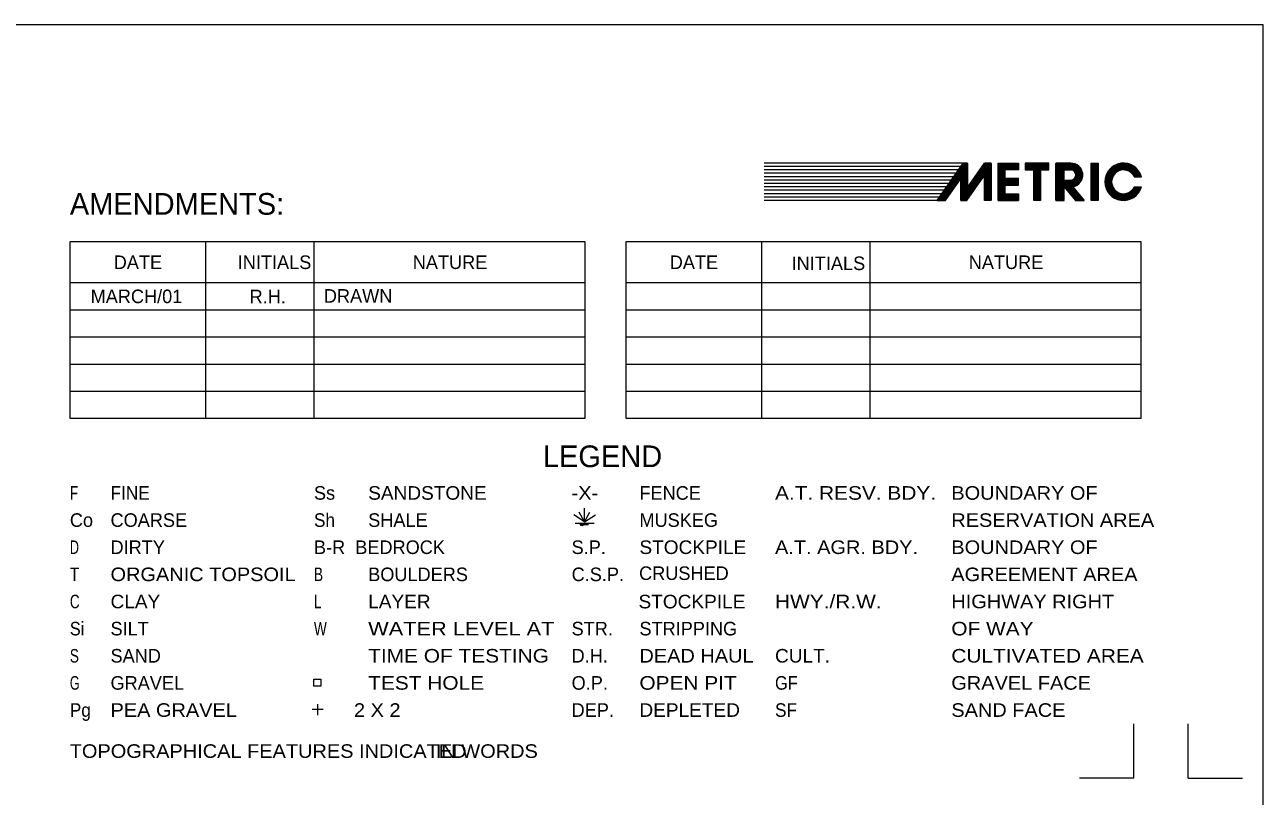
# Model space of a CAD drawing. Extents: x -496 to 480, y -450 to 700.
# Drawn here: x -6.6 to 450, y 415.7 to 700 of the extents above; entities that cross this region are included whole.
import ezdxf
from ezdxf.enums import TextEntityAlignment as Align

# ---------------------------------------------------------------- set-up
doc = ezdxf.new("R2010")
doc.units = 0
doc.header["$LTSCALE"] = 2
doc.header["$PDMODE"] = 32
doc.header["$PDSIZE"] = 1
doc.layers.add('1', color=7, linetype='Continuous', lineweight=13)

msp = doc.modelspace()

# ---------------------------------------------------------------- linework, layer by layer
at = {"layer": '1'}
for p, q in [((339.376, 648.989), (265.976, 648.989)), ((329.726, 635.239), (339.376, 648.989)), ((340.976, 640.064), (347.226, 648.989)), ((349.726, 648.989), (347.226, 648.989)), ((349.726, 635.239), (349.726, 648.989)), ((362.226, 648.989), (362.226, 646.489)), ((379.026, 648.989), (373.476, 648.989)), ((338.501, 647.739), (265.976, 647.739)), ((337.626, 646.489), (265.976, 646.489)), ((336.751, 645.239), (265.976, 645.239)), ((335.876, 643.989), (265.976, 643.989)), ((340.676, 635.264), (347.226, 644.614)), ((347.226, 635.239), (347.226, 644.614)), ((354.726, 646.489), (354.726, 643.364)), ((362.226, 646.489), (365.351, 646.489)), ((367.851, 646.489), (370.976, 646.489)), ((376.601, 646.489), (379.151, 646.489)), ((376.601, 642.739), (376.601, 646.489)), ((402.426, 643.989), (405.076, 643.989)), ((335.001, 642.739), (265.976, 642.739)), ((334.126, 641.489), (265.976, 641.489)), ((333.251, 640.239), (265.976, 640.239)), ((332.776, 635.239), (338.476, 643.364)), ((338.476, 635.239), (338.476, 643.389)), ((354.726, 640.864), (354.726, 637.739)), ((376.601, 642.739), (379.151, 642.739)), ((376.601, 640.239), (380.726, 635.239)), ((376.601, 635.239), (376.601, 640.239)), ((379.801, 640.289), (383.951, 635.239)), ((402.426, 640.239), (405.101, 640.239)), ((332.376, 638.989), (265.976, 638.989)), ((331.501, 637.739), (265.976, 637.739)), ((330.626, 636.489), (265.976, 636.489)), ((329.726, 635.239), (265.976, 635.239)), ((329.726, 635.239), (332.776, 635.239)), ((338.476, 635.239), (340.676, 635.239)), ((349.726, 635.239), (347.226, 635.239)), ((352.226, 635.239), (359.726, 635.239)), ((380.726, 635.239), (383.951, 635.239)), ((199.983, 619.973), (9.983, 619.973)), ((9.983, 619.973), (9.983, 554.973)), ((59.983, 619.973), (59.983, 554.973)), ((99.983, 619.973), (99.983, 554.973)), ((199.983, 554.973), (199.983, 619.973)), ((404.983, 619.973), (214.983, 619.973)), ((214.983, 619.973), (214.983, 554.973)), ((264.983, 619.973), (264.983, 554.973)), ((304.983, 619.973), (304.983, 554.973)), ((404.983, 554.973), (404.983, 619.973)), ((9.983, 604.973), (199.983, 604.973)), ((214.983, 604.973), (404.983, 604.973)), ((9.983, 594.973), (199.983, 594.973)), ((214.983, 594.973), (404.983, 594.973)), ((9.983, 584.973), (199.983, 584.973)), ((214.983, 584.973), (404.983, 584.973)), ((9.983, 574.973), (199.983, 574.973)), ((214.983, 574.973), (404.983, 574.973)), ((9.983, 564.973), (199.983, 564.973)), ((214.983, 564.973), (404.983, 564.973)), ((214.983, 554.973), (404.983, 554.973)), ((199.76, 516.875), (199.76, 521.875)), ((199.76, 516.875), (195.76, 519.375)), ((196.26, 516.375), (203.26, 516.375)), ((199.76, 516.875), (197.76, 520.375)), ((199.76, 516.875), (201.76, 520.375)), ((199.76, 516.875), (203.76, 519.375)), ((198.26, 515.875), (201.26, 515.875)), ((103.353, 447.618), (99.353, 447.618)), ((101.291, 449.597), (101.291, 445.597)), ((402.281, 422.339), (402.281, 442.339)), ((422.281, 422.339), (422.281, 442.339)), ((402.281, 422.339), (382.281, 422.339)), ((422.281, 422.339), (442.281, 422.339))]:
    msp.add_line(p, q, dxfattribs=at)
for points in [[(449.983, -450.027), (449.983, 399.973), (449.983, 699.973), (-450.017, 699.973), (-450.017, 49.973), (-450.017, -450.027)], [(329.901, 635.339), (339.401, 648.889), (340.901, 648.889), (340.901, 639.839), (347.251, 648.839), (349.626, 648.889), (349.676, 635.339), (347.351, 635.314), (347.301, 644.789), (340.576, 635.339), (338.576, 635.314), (338.576, 643.539), (332.701, 635.339), (330.076, 635.314), (339.501, 648.739), (340.801, 648.739), (340.776, 639.664), (347.276, 648.664), (349.526, 648.739), (349.651, 635.564), (347.501, 635.464), (347.426, 644.989), (340.526, 635.489), (338.726, 635.439), (338.676, 643.764), (332.651, 635.464), (330.301, 635.439), (339.576, 648.539), (340.651, 648.564), (340.651, 639.489), (347.351, 648.489), (349.301, 648.564), (349.476, 635.739), (347.726, 635.639), (347.626, 645.314), (340.451, 635.714), (338.926, 635.639), (338.876, 644.139), (332.501, 635.689), (330.701, 635.639)], [(340.976, 640.039), (340.976, 648.989), (339.376, 648.989)], [(352.226, 635.239), (352.226, 648.989), (359.726, 648.989)], [(352.376, 648.914), (359.651, 648.864), (359.676, 646.614), (354.626, 646.589), (354.626, 643.289), (359.651, 643.289), (359.651, 640.989), (354.651, 640.939), (354.626, 637.614), (359.676, 637.639), (359.651, 635.339), (352.351, 635.314), (352.376, 648.789), (359.551, 648.739), (359.551, 646.764), (354.501, 646.714), (354.501, 643.214), (359.551, 643.164), (359.551, 641.114), (354.551, 641.064), (354.526, 637.439), (359.551, 637.514), (359.501, 635.439), (352.501, 635.439), (352.576, 648.639), (359.401, 648.564), (359.426, 646.914), (354.376, 646.839), (354.351, 643.064), (359.426, 643.039), (359.376, 641.289), (354.401, 641.239), (354.376, 637.239), (359.401, 637.339), (359.376, 635.589), (352.701, 635.614), (352.726, 648.439), (359.226, 648.414), (359.251, 647.064), (354.251, 647.039)], [(359.726, 648.989), (359.726, 646.489), (354.726, 646.489)], [(370.976, 646.489), (370.976, 648.989), (362.226, 648.989)], [(362.351, 648.864), (370.851, 648.889), (370.851, 646.639), (367.701, 646.639), (367.751, 635.414), (365.451, 635.314), (365.451, 646.564), (362.351, 646.589), (362.351, 648.764), (370.801, 648.789), (370.726, 646.789), (367.601, 646.764), (367.676, 635.539), (365.576, 635.414), (365.626, 646.739), (362.476, 646.739), (362.476, 648.639), (370.626, 648.639), (370.576, 646.989), (367.426, 646.864), (367.526, 635.739), (365.751, 635.614), (365.776, 646.864), (362.701, 646.939), (362.726, 648.439), (370.451, 648.489), (370.376, 647.114), (367.276, 646.989), (367.376, 635.914), (365.901, 635.789), (365.951, 647.064), (362.901, 647.114), (362.901, 648.264), (370.201, 648.289), (370.201, 647.364), (367.076, 647.189), (367.226, 636.114), (366.126, 635.989), (366.101, 647.264), (363.101, 647.314)], [(373.476, 648.989), (373.476, 635.239), (376.601, 635.239)], [(373.601, 648.914), (378.976, 648.889), (380.101, 648.739), (381.101, 648.364), (381.826, 647.789), (382.451, 647.189), (382.901, 646.414), (383.301, 645.389), (383.301, 644.439), (383.126, 643.214), (382.651, 642.314), (381.926, 641.489), (381.051, 640.889), (380.401, 640.639), (379.651, 640.389), (380.026, 639.714), (380.576, 639.189), (383.701, 635.339), (380.801, 635.314), (376.501, 640.464), (376.526, 635.339), (373.551, 635.314), (373.551, 648.864), (379.026, 648.789), (380.076, 648.639), (380.926, 648.314), (382.276, 647.214), (383.151, 645.364), (383.026, 643.314), (382.601, 642.464), (381.901, 641.614), (381.051, 640.989), (379.576, 640.464), (383.501, 635.414), (380.951, 635.439), (376.351, 640.739), (376.401, 635.489), (373.701, 635.439), (373.701, 648.739), (379.151, 648.664), (380.076, 648.489), (380.851, 648.189), (382.126, 647.139), (383.026, 645.389), (382.951, 643.539), (382.501, 642.564), (381.901, 641.739), (381.051, 641.114), (379.401, 640.614), (383.201, 635.564), (381.001, 635.564), (376.226, 640.889), (376.276, 635.614), (373.826, 635.539), (373.826, 648.614), (379.126, 648.489), (380.676, 648.089), (382.026, 647.139), (382.876, 645.439), (382.801, 643.664), (382.401, 642.664), (381.801, 641.889), (380.951, 641.189), (379.226, 640.764), (382.901, 635.689), (381.101, 635.689), (376.051, 641.064), (376.126, 635.789), (373.976, 635.689), (373.976, 648.439), (379.101, 648.364), (380.551, 647.989), (381.851, 647.089), (382.776, 645.439), (382.701, 643.764), (382.326, 642.889), (381.726, 642.064), (380.901, 641.339), (379.026, 640.939), (382.601, 635.789), (381.126, 635.814), (375.876, 641.239), (375.976, 635.939), (374.126, 635.864), (374.126, 648.239), (379.026, 648.239), (380.251, 647.914), (381.676, 647.014), (382.576, 645.414), (382.601, 643.914), (382.276, 642.989), (381.651, 642.214), (380.826, 641.514), (378.851, 641.064), (382.351, 635.939), (381.176, 635.989), (375.776, 641.514), (375.826, 636.089), (374.251, 636.014), (374.276, 648.039), (378.976, 648.114)], [(386.776, 648.839), (388.951, 648.864), (389.001, 635.364), (386.701, 635.364), (386.676, 648.739), (388.851, 648.764), (388.876, 635.489), (386.826, 635.439), (386.801, 648.614), (388.776, 648.639), (388.776, 635.664), (386.976, 635.589), (386.926, 648.464), (388.626, 648.464), (388.601, 635.764), (387.126, 635.764), (387.101, 648.364), (388.501, 648.364), (388.451, 635.939), (387.301, 635.964), (387.301, 648.214), (388.401, 648.214), (388.301, 636.089), (387.426, 636.089), (387.476, 648.064), (388.251, 648.039), (388.151, 636.214), (387.576, 636.214), (387.676, 647.914), (388.126, 647.889), (388.001, 636.339), (387.776, 636.389), (387.826, 647.764), (387.976, 647.714), (387.901, 636.539)], [(404.901, 644.089), (404.451, 645.189), (403.851, 646.164), (403.151, 646.914), (402.301, 647.639), (401.151, 648.289), (400.126, 648.614), (398.801, 648.814), (397.351, 648.689), (395.876, 648.339), (394.601, 647.639), (393.601, 646.764), (392.776, 645.664), (392.176, 644.564), (391.801, 642.964), (391.801, 641.264), (392.176, 639.789), (392.726, 638.564), (393.351, 637.739), (394.101, 637.014), (394.976, 636.389), (395.901, 635.914), (397.126, 635.489), (398.726, 635.389), (400.151, 635.589), (401.301, 635.989), (402.326, 636.564), (403.326, 637.414), (404.001, 638.264), (404.426, 639.139), (404.801, 640.064), (402.526, 640.089), (401.776, 638.989), (400.776, 638.289), (399.801, 637.814), (398.476, 637.564), (397.026, 637.839), (396.126, 638.289), (395.276, 638.939), (394.551, 639.939), (394.076, 641.189), (394.051, 642.814), (394.276, 643.889), (394.901, 644.889), (395.601, 645.614), (396.476, 646.164), (397.376, 646.489), (398.426, 646.614), (399.526, 646.489), (400.426, 646.214), (401.176, 645.764), (401.801, 645.239), (402.301, 644.664), (402.576, 644.139), (404.726, 644.164), (404.251, 645.214), (403.651, 646.164), (402.276, 647.489), (401.126, 648.114), (399.351, 648.614), (397.876, 648.564), (396.551, 648.339), (395.226, 647.814), (394.351, 647.264), (393.451, 646.339), (392.676, 645.139), (392.176, 643.939), (391.976, 642.239), (392.076, 640.689), (392.576, 639.164), (393.476, 637.864), (394.526, 636.864), (395.701, 636.164), (397.201, 635.639), (398.626, 635.514), (400.251, 635.764), (401.276, 636.089), (402.301, 636.789), (403.176, 637.439), (403.726, 638.164), (404.376, 639.239), (404.551, 639.964), (402.626, 639.989), (402.076, 639.064), (400.751, 638.139), (399.826, 637.689), (398.526, 637.389), (396.976, 637.739), (395.601, 638.439), (394.651, 639.639), (394.076, 640.764), (393.876, 642.139), (394.151, 643.989), (394.726, 644.964), (395.826, 646.014), (397.051, 646.539), (398.351, 646.789), (399.826, 646.614), (401.026, 646.064), (401.701, 645.614), (402.226, 645.014)], [(402.226, 645.014), (402.301, 645.014), (402.676, 644.239), (404.476, 644.264), (404.026, 645.314), (402.876, 646.664), (401.901, 647.489), (400.851, 648.089), (399.251, 648.514), (396.976, 648.264), (395.201, 647.614), (394.051, 646.639), (393.151, 645.614), (392.526, 644.239), (392.176, 642.439), (392.326, 640.539), (392.676, 639.489), (392.951, 638.864), (393.701, 637.864), (394.851, 636.839), (397.101, 635.814), (398.651, 635.664), (401.026, 636.164), (403.076, 637.564), (403.901, 638.814), (404.326, 639.814), (403.476, 639.789), (402.726, 639.839), (402.201, 638.889), (400.776, 637.964), (399.526, 637.414), (398.251, 637.264), (396.651, 637.714), (395.476, 638.364), (394.451, 639.714), (393.901, 640.864), (393.701, 642.264), (393.976, 643.889), (394.651, 645.264), (395.701, 646.214), (397.376, 646.789), (398.851, 646.914), (400.251, 646.614), (401.626, 645.914), (402.426, 645.164), (402.801, 644.439), (404.226, 644.414), (403.426, 645.739), (402.676, 646.614), (401.826, 647.314), (400.851, 647.939), (399.276, 648.314), (397.051, 648.089), (395.226, 647.364), (393.976, 646.314), (393.201, 645.414), (392.651, 643.839), (392.426, 642.514), (392.451, 641.239), (392.651, 640.089), (393.101, 639.039), (393.651, 638.239), (394.376, 637.564), (395.226, 636.839), (396.351, 636.314), (397.451, 635.914), (398.701, 635.839), (400.826, 636.364), (402.976, 637.639), (403.801, 638.964), (404.026, 639.714), (402.851, 639.664), (402.326, 638.814), (401.226, 638.164), (399.651, 637.239), (398.226, 637.114), (397.101, 637.389), (395.976, 637.889), (394.801, 638.989), (394.101, 640.014), (393.601, 641.664), (393.676, 643.264), (394.101, 644.689), (395.376, 646.214), (396.876, 646.764), (398.751, 647.064), (400.326, 646.764), (401.751, 646.089), (402.651, 645.189), (402.951, 644.539), (403.876, 644.614), (403.051, 645.989), (402.201, 646.789), (400.851, 647.739), (399.376, 648.189), (397.151, 647.889), (395.451, 647.239), (394.076, 646.164), (393.251, 645.039), (392.701, 643.014), (392.651, 641.564)], [(330.701, 635.639), (339.651, 648.239), (340.326, 648.264), (340.476, 639.239), (347.526, 648.239), (349.126, 648.289), (349.226, 635.939), (348.001, 635.939), (347.851, 645.664), (340.326, 635.989), (339.151, 635.864), (339.126, 644.464), (332.401, 635.939), (331.076, 635.839), (339.651, 647.914), (340.151, 647.914), (340.251, 638.889), (347.601, 647.964), (348.926, 648.014), (349.026, 636.164), (348.251, 636.139), (348.051, 646.014), (340.226, 636.239), (339.351, 636.089), (339.326, 644.789), (332.226, 636.164), (331.476, 636.064), (339.701, 647.664), (339.926, 647.689), (340.126, 638.764), (347.751, 647.839), (348.701, 647.739), (348.826, 636.364), (348.476, 636.364), (348.176, 646.314), (340.126, 636.464), (339.551, 636.339), (339.426, 645.114), (332.201, 636.339), (331.851, 636.289)], [(331.851, 636.289), (339.701, 647.264), (339.926, 638.564), (347.826, 647.614), (348.451, 647.589), (348.701, 636.589), (348.251, 646.639), (340.126, 636.689), (339.726, 636.589), (339.576, 645.539), (332.301, 636.639), (339.526, 646.714), (339.576, 645.814), (335.101, 640.239), (339.401, 646.164), (339.401, 645.914), (338.176, 644.289)], [(339.901, 638.414), (339.926, 636.839), (348.276, 646.889), (348.326, 647.439), (347.951, 647.439), (340.126, 638.539), (340.151, 637.314), (348.176, 647.064), (348.051, 647.214), (340.326, 638.539), (340.401, 637.839), (347.851, 646.839), (340.501, 638.639), (340.526, 638.389), (344.426, 642.914)], [(354.251, 647.039), (354.176, 642.864), (359.251, 642.864), (359.176, 641.439), (354.251, 641.389), (354.201, 637.064), (359.201, 637.114), (359.176, 635.739), (352.926, 635.814), (352.976, 648.214), (359.026, 648.239), (359.076, 647.289), (354.076, 647.214), (354.001, 642.689), (359.051, 642.664), (359.026, 641.639), (354.076, 641.564), (354.026, 636.864), (359.051, 636.939), (359.026, 635.989), (353.126, 636.039), (353.226, 647.989), (358.801, 648.039), (358.826, 647.464), (353.926, 647.389), (353.851, 642.489), (358.876, 642.539), (358.801, 641.814), (353.951, 641.689), (353.851, 636.714), (358.901, 636.764), (358.901, 636.214), (353.351, 636.214), (353.476, 647.714), (358.601, 647.889), (358.626, 647.639), (353.776, 647.514), (353.751, 642.364), (358.626, 642.389), (358.601, 642.014)], [(358.601, 642.014), (353.826, 641.864), (353.726, 636.564), (358.701, 636.639), (358.701, 636.389), (353.551, 636.439), (353.626, 641.989), (358.376, 642.164), (358.326, 642.289), (353.576, 642.264), (353.676, 647.564)], [(363.101, 647.314), (363.151, 648.089), (369.976, 648.164), (369.926, 647.489), (366.876, 647.364), (367.026, 636.339), (366.351, 636.239), (366.276, 647.439), (363.326, 647.514), (363.401, 647.939), (369.751, 648.039), (369.701, 647.714), (366.726, 647.539), (366.851, 636.564), (366.476, 636.489), (366.426, 647.664), (363.701, 647.664), (363.751, 647.839), (369.451, 647.914), (369.426, 647.814), (366.601, 647.664), (366.626, 636.689)], [(367.851, 646.489), (367.851, 635.239), (365.351, 635.239), (365.351, 646.489)], [(378.976, 648.114), (379.026, 648.114), (380.201, 647.764), (381.526, 646.939), (382.401, 645.489), (382.401, 643.964), (382.076, 643.114), (380.826, 641.764), (378.601, 641.264), (382.001, 636.114), (381.351, 636.114), (375.676, 641.789), (375.676, 636.264), (374.376, 636.189), (374.451, 647.864), (378.926, 647.939), (380.176, 647.689), (381.351, 646.914), (382.151, 645.414), (382.201, 644.014), (381.901, 643.214), (380.726, 641.989), (378.401, 641.389), (381.676, 636.314), (381.501, 636.189), (375.526, 642.064), (375.476, 636.414), (374.551, 636.339), (374.651, 647.739), (379.976, 647.614), (381.151, 646.914), (382.001, 645.414), (382.051, 644.139), (381.726, 643.339), (380.651, 642.139), (378.226, 641.589), (381.401, 636.464), (375.401, 642.364), (375.376, 636.614), (374.676, 636.539), (374.901, 647.589), (379.826, 647.414), (380.851, 646.889), (381.801, 645.439), (381.901, 644.389), (381.576, 643.539), (380.576, 642.414), (378.051, 641.739), (380.676, 637.364), (375.376, 642.614), (375.226, 636.739), (374.851, 636.739), (375.076, 647.339), (379.601, 647.314), (380.676, 646.839), (381.626, 645.414), (381.726, 644.464), (381.376, 643.589), (380.501, 642.589), (377.826, 641.864), (380.026, 638.189), (375.251, 642.889), (375.076, 636.939), (374.926, 636.989), (375.226, 647.189), (379.526, 647.139), (380.551, 646.714), (381.401, 645.414), (381.551, 644.614), (380.376, 642.739), (377.726, 642.039), (379.276, 639.239), (375.351, 643.039), (375.426, 646.989), (379.476, 646.989), (380.526, 646.639), (381.251, 645.489), (381.326, 644.614), (380.276, 642.914), (377.551, 642.239), (378.601, 640.139), (375.576, 643.139), (375.676, 646.839), (379.451, 646.839), (380.476, 646.514), (381.101, 645.414), (381.051, 644.489), (380.876, 645.464), (380.501, 646.039), (380.151, 646.339), (379.476, 646.514), (378.751, 646.639), (377.601, 646.614), (376.476, 646.614), (376.501, 642.714), (378.626, 642.664), (377.376, 642.339), (378.126, 640.764), (375.726, 643.164), (375.876, 646.714), (379.451, 646.714)], [(376.026, 646.614), (375.901, 643.214), (377.551, 641.614), (377.251, 642.364), (377.776, 642.614), (376.826, 642.614), (377.201, 642.164)], [(376.151, 646.564), (376.051, 643.314), (376.376, 643.064), (376.351, 646.564), (376.251, 643.389)], [(379.451, 646.714), (379.401, 646.739), (380.451, 646.289)], [(392.651, 641.564), (392.676, 641.614), (392.951, 639.914), (393.451, 638.964), (394.051, 638.214), (394.926, 637.289), (395.951, 636.764), (396.601, 636.389), (397.801, 636.039), (398.776, 635.989), (400.726, 636.464), (402.951, 637.739), (403.651, 639.064), (403.726, 639.564), (403.026, 639.539), (402.576, 638.814), (399.876, 637.114), (398.026, 637.014), (396.051, 637.664), (394.476, 639.139), (393.526, 641.439), (393.651, 643.889), (394.476, 645.514), (395.726, 646.539), (397.351, 646.989), (398.701, 647.239), (400.476, 646.939), (401.751, 646.339), (402.526, 645.664), (402.851, 645.114), (403.076, 644.739), (403.551, 644.789), (402.926, 645.989), (401.801, 646.914), (400.676, 647.639), (399.376, 648.039), (397.176, 647.789), (395.676, 647.164), (394.226, 646.139), (393.501, 645.039), (392.901, 643.314), (392.826, 641.639), (393.126, 639.989), (393.851, 638.689), (394.951, 637.514), (396.001, 636.989), (396.726, 636.564), (398.626, 636.139), (400.701, 636.614), (402.776, 637.864), (403.476, 639.064), (403.601, 639.464), (403.251, 639.389), (402.751, 638.739), (400.001, 637.014), (398.001, 636.889), (395.901, 637.564), (394.326, 639.064), (393.376, 641.464), (393.576, 643.939), (394.301, 645.589), (395.526, 646.689), (398.576, 647.339), (400.751, 647.089), (401.751, 646.489), (402.601, 645.914), (403.076, 645.039), (403.326, 644.914), (402.851, 645.939), (400.926, 647.289), (399.526, 647.889), (397.401, 647.714), (395.626, 647.039), (394.251, 646.039), (393.576, 644.889), (393.026, 643.239), (392.951, 641.714), (393.276, 640.314), (393.801, 639.139), (394.376, 638.339), (395.076, 637.639), (396.901, 636.764), (398.651, 636.314), (400.576, 636.789), (402.601, 637.914), (403.351, 639.139), (402.501, 638.339), (401.601, 637.789), (400.101, 636.864), (398.051, 636.764), (395.801, 637.439), (394.176, 639.064), (393.226, 641.539), (393.501, 644.014), (394.126, 645.639), (395.451, 646.739), (397.026, 647.189), (398.576, 647.489), (399.776, 647.389), (400.526, 647.289), (399.551, 647.639)], [(402.751, 638.439), (402.076, 637.814), (400.676, 637.089), (399.226, 636.639), (398.501, 636.639), (396.951, 636.914), (395.751, 637.364), (394.201, 638.764), (393.101, 641.589), (393.401, 643.964), (393.901, 645.289)], [(399.551, 647.639), (398.601, 647.639), (397.451, 647.489), (395.901, 647.064)], [(354.726, 640.864), (359.726, 640.864), (359.726, 643.364), (354.726, 643.364)], [(354.726, 637.739), (359.726, 637.739), (359.726, 635.239)], [(9.983, 554.973), (99.983, 554.973), (199.983, 554.973)]]:
    msp.add_lwpolyline(points, dxfattribs=at)
for points in [[(386.601, 635.239), (386.601, 648.989), (389.101, 648.989), (389.101, 635.239)], [(99.967, 456.301), (99.967, 458.832), (102.499, 458.832), (102.499, 456.301)]]:
    msp.add_lwpolyline(points, close=True, dxfattribs=at)
for centre, radius, start, end in [((379.076, 644.614), 4.375, 279.51602, 90.65478), ((398.476, 642.114), 6.875, 15.80251, 344.19749), ((379.051, 644.614), 1.875, 272.29061, 86.94712), ((398.476, 642.114), 4.375, 25.39292, 334.60708)]:
    msp.add_arc(centre, radius, start, end, dxfattribs=at)
msp.add_point((198.76, 515.875), dxfattribs=at)

# ---------------------------------------------------------------- texts
for s, height, p in [('AMENDMENTS:', 8, (9.983, 629.973)), ('Ss', 5, (99.983, 524.973)), ('FENCE', 5, (219.983, 524.973)), ('Co', 5, (9.983, 514.973)), ('COARSE', 5, (24.983, 514.973)), ('SHALE', 5, (119.983, 514.973)), ('MUSKEG', 5, (219.983, 514.973)), ('DIRTY', 5, (24.983, 504.973)), ('B-R  BEDROCK', 5, (99.983, 504.973)), ('S.P.', 5, (194.983, 504.973)), ('BOULDERS', 5, (119.983, 494.973)), ('C.S.P.', 5, (194.983, 494.973)), ('CRUSHED', 5, (219.856, 495.402)), ('SILT', 5, (24.983, 474.973)), ('STR.', 5, (194.983, 474.973)), ('STRIPPING', 5, (219.983, 474.973)), ('SAND', 5, (24.983, 464.973)), ('D.H.', 5, (194.983, 464.973)), ('GRAVEL', 5, (24.983, 454.973)), ('O.P.', 5, (194.983, 454.973)), ('DEP.', 5, (194.983, 444.973))]:
    msp.add_text(s, height=height, dxfattribs=at).set_placement(p)
for s, height, p in [('DATE', 5, (35.081, 609.973)), ('INITIALS', 5, (85.453, 609.973)), ('NATURE', 5, (150.16, 609.973)), ('DATE', 5, (240.081, 609.973)), ('INITIALS', 5, (289.66, 609.584)), ('NATURE', 5, (355.16, 609.973)), ('MARCH/01', 5, (34.552, 597.405)), ('R.H.', 5, (82.941, 597.343)), ('DRAWN', 5, (116.266, 597.567)), ('LEGEND', 8, (206.378, 536.973))]:
    msp.add_text(s, height=height, dxfattribs=at).set_placement(p, align=Align.CENTER)
for s, width, p in [('F', 0.75, (9.983, 524.973)), ('FINE', 0.95, (24.983, 524.973)), ('SANDSTONE', 1.05, (119.983, 524.973)), ('-X-', 1.1, (194.983, 524.973)), ('A.T. RESV. BDY.', 1.15, (269.983, 524.973)), ('BOUNDARY OF', 1.1, (334.983, 524.973)), ('Sh', 0.95, (99.983, 514.973)), ('RESERVATION AREA', 1.1, (334.983, 514.973)), ('D', 0.7, (9.983, 504.973)), ('STOCKPILE', 1.05, (219.983, 504.973)), ('A.T. AGR. BDY.', 1.1, (269.983, 504.973)), ('BOUNDARY OF', 1.1, (334.983, 504.973)), ('T', 0.85, (9.983, 494.973)), ('ORGANIC TOPSOIL', 1.1, (24.983, 494.973)), ('B', 0.75, (99.983, 494.973)), ('AGREEMENT AREA', 1.1, (334.983, 494.973)), ('C', 0.75, (9.983, 484.973)), ('CLAY', 1.05, (24.983, 484.973)), ('L', 0.75, (99.983, 484.973)), ('LAYER', 1.05, (119.983, 484.973)), ('STOCKPILE', 1.05, (219.649, 484.941)), ('HWY./R.W.', 1.15, (269.983, 484.973)), ('HIGHWAY RIGHT', 1.1, (334.983, 484.973)), ('Si', 0.9, (9.983, 474.973)), ('W', 0.75, (99.983, 474.973)), ('WATER LEVEL AT', 1.2, (119.983, 474.973)), ('OF WAY', 1.15, (334.983, 474.973)), ('S', 0.75, (9.983, 464.973)), ('TIME OF TESTING', 1.15, (119.983, 464.973)), ('DEAD HAUL', 1.1, (219.983, 464.973)), ('CULT.', 1.05, (269.983, 464.973)), ('CULTIVATED AREA', 1.15, (334.983, 464.973)), ('G', 0.7, (9.983, 454.973)), ('TEST HOLE', 1.15, (119.983, 454.973)), ('OPEN PIT', 1.15, (219.983, 454.973)), ('GF', 0.9, (269.983, 454.973)), ('GRAVEL FACE', 1.1, (334.983, 454.973)), ('Pg', 0.95, (9.983, 444.973)), ('PEA GRAVEL', 1.1, (24.983, 444.973)), ('   2 X 2', 1.1, (108.608, 444.973)), ('DEPLETED', 1.05, (219.983, 444.973)), ('SF', 0.95, (269.983, 444.973)), ('SAND FACE', 1.1, (334.983, 444.973)), ('TOPOGRAPHICAL FEATURES INDICATED', 1.1, (9.942, 429.855)), ('IN WORDS', 1.1, (144.942, 429.855))]:
    msp.add_text(s, height=5, dxfattribs=dict(at, width=width)).set_placement(p)

doc.saveas('drawing.dxf')
